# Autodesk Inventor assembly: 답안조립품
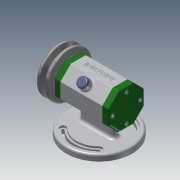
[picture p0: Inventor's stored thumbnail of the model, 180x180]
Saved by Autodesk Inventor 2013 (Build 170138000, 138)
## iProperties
Created: 2017-06
Part Number: 답안조립품
Document SubType Name: Assembly
Designer: Administrator
Author: Administrator
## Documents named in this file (14)
- C:\Users\Administrator\Desktop\470608V1017\답안조립품.iam
- C:\Users\Administrator\Desktop\470608V1017\본체.ipt
- C:\Users\Administrator\Desktop\470608V1017\축.ipt
- C:\Users\Administrator\Desktop\470608V1017\베어링 15 x 32 x 9.ipt
- C:\Users\Administrator\Desktop\470608V1017\뒤커버.ipt
- C:\Users\Administrator\Desktop\470608V1017\앞커버.ipt
- C:\Users\Administrator\Desktop\470608V1017\키 3 x 3 x 12.ipt
- C:\Users\Administrator\Desktop\470608V1017\V벨트풀리.ipt
- C:\Users\Administrator\Desktop\470608V1017\와셔 8x17.ipt
- C:\Users\Administrator\Desktop\470608V1017\스프링와셔 8.ipt
- C:\Users\Administrator\Desktop\470608V1017\너트 M 8.ipt
- C:\Users\Administrator\Desktop\470608V1017\고무캡.ipt
- C:\Users\Administrator\Desktop\470608V1017\볼트 M4 x 12.ipt
- C:\Users\Administrator\Desktop\470608V1017\오일 실 15 25 7.ipt
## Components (2 placed, 2 different names)
1. V벨트풀리:1
2. 고무캡:1
